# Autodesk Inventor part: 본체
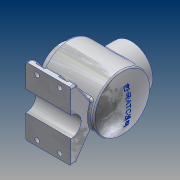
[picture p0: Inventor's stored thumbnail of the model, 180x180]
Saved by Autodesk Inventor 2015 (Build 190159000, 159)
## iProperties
Created: 2017-04
Part Number: 본체
Material: 알루미늄 6061
Document SubType Name: Modeling
Designer: owner
Density: 2.7 g/cm^3
Appearance: 알루미늄 - 평지
Mass: 1664.46 g
Surface Area: 1066.88 cm^2
Volume: 616.468 cm^3
Author: owner
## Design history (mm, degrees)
sketch "스케치1"
  geometry: L1 (-60, 0)-(60, 0); L2 (-60, 0)-(-60, 38); L3 (-60, 38)-(-51, 38); L4 (-48, 41)-(-48, 47); L5 (-45, 50)-(46.454, 50); L6 (-60, 27)-(-38, 27); L7 (-38, 27)-(-38, 37); L8 (-35, 40)-(39.903, 40); L9 (-53, 7.069)-(-53, -16.62); A1 r 3 centre (-45, 47) between (-45, 50) and (-48, 47); A2 r 3 centre (-51, 41) between (-51, 38) and (-48, 41); A3 r 3 centre (-35, 37) between (-35, 40) and (-38, 37); A4 r 113 centre (-53, 0) between (60, 0) and (49.166, 48.282); A5 r 103 centre (-53, 0) between (50, 0) and (42.69, 38.11); A6 r 3 centre (39.903, 37) between (42.69, 38.11) and (39.903, 40); A7 r 3 centre (46.454, 47) between (49.166, 48.282) and (46.454, 50); 5 further points
  constraints: 18 end point, 16 point on circle, 10 tangent, 8 point on line, 7 centre point, 5 perpendicular, 3 equal radius, 2 coincident, 2 horizontal, 2 vertical, 1 midpoint
  dimensions: "d0" = 120 distance of L1.end L1.start; "d3" = 76 diameter of L3 L1; "d4" = 54 diameter of L6 L1; "d5" = 22 distance of L6.start L6.end; "d6" = 12 distance of L2.end point (-48, 38); "d7" = 100 diameter of L5 L1; "d8" = 80 diameter of L8 L1; "d9" = 3 radius of A1; "d14" = 113 distance from line of L9 L1.end; "d15" = 113 radius of A4 (derived); "d16" = 103 radius of A5; "d17" = 3 radius of A6
revolve "회전1" sketch "스케치1" stored, may be unused: angle "d18" = 90 deg
chamfer "모따기1" distance "d19" = 1; stored, may be unused: second distance "d20" = 2, angle "d21" = 45 deg
node "작업 평면1"
sketch "스케치2"
  geometry: C1 r 38 at (0, 0); C2 r 27 at (0, 0); 1 further point
  constraints: 2 centre point, 2 coincident
  dimensions: "d23" = 76 diameter of C1; "d24" = 54 diameter of C2
extrude "돌출1" join sketch "스케치2" stored distance "d25" = 10; taper "d26" = 0 deg
extrude "돌출2" cut sketch "스케치2" stored distance "d27" = 10; taper "d28" = 0 deg
chamfer "모따기2" distance "d29" = 1; stored, may be unused: second distance "d30" = 2, angle "d31" = 45 deg
sketch "스케치3"
  geometry: C1 r 38 at (0, 0) reference; 1 further point
  constraints: 1 vertical alignment
  dimensions: "d32" = 32.5 distance of C1.centre point (0, 32.5)
hole "구멍1" sketch "스케치3" at (0, 32.5) diameter "d33" = 3.242; stored, may be unused: countersink angle "d37" = 90 deg, drill point angle "d39" = 118 deg; dims "d34" = 8, "d35" = 4, "d36" = 2, "d38" = 10
sketch "스케치4"
  geometry: C1 r 38 at (0, 0) reference; 1 further point
  constraints: 1 vertical alignment
  dimensions: "d43" = 32.5 distance of C1.centre point (0, 32.5)
hole "구멍2" sketch "스케치4" at (0, 32.5) diameter "d44" = 3.242; stored, may be unused: countersink angle "d48" = 90 deg, drill point angle "d50" = 118 deg; dims "d45" = 8, "d46" = 4, "d47" = 2, "d49" = 10
sketch "스케치5"
  geometry: L1 (-82, -60)-(-72, -60); L2 (-72, -60)-(-45.101, -21.584); L3 (-82, 60)-(-72, 60); L4 (-72, 60)-(-45.101, 21.584); L5 (-82, -60)-(-82, -18); L6 (-82, 18)-(-82, 60); A1 r 50 centre (0, 0) between (-45.101, -21.584) and (-45.101, 21.584) reference; A2 r 18 centre (-82, 0) between (-82, -18) and (-82, 18); 2 further points
  constraints: 12 end point, 4 point on circle, 2 horizontal, 2 vertical, 1 centre point, 1 coincident, 1 collinear, 1 horizontal alignment
  dimensions: "d54" = 120 distance of L1.start L3.start; "d56" = 10 distance of L1.start L1.end; "d57" = 36 diameter of A2; "d58" = 82 distance from line of L6 point (0, 0); "d59" = 82 distance of point (-82, 0) point (0, 0); "d60" = 10 distance from line of L6 L3.end; "d61" = 55 deg angle of L1 L2; "d62" = 55 deg angle of L3 L4; "d63" = 38.41556 vertical distance of L3.end L4.end
extrude "돌출3" join sketch "스케치5" stored distance "d64" = 80; taper "d65" = 0 deg
sketch "스케치6"
  geometry: L1 (80, 0)-(0, 0) reference; L2 (20, -15.656)-(20, 10); L3 (28, 0)-(28, 10); L4 (12, 10)-(12, 0); L5 (12, 0)-(28, 0); C1 r 4 at (20, 10); A1 r 8 centre (20, -15.656) between (12, -15.656) and (28, -15.656); A2 r 8 centre (20, 10) between (28, 10) and (12, 10); 2 further points
  constraints: 10 end point, 4 point on circle, 4 tangent, 3 centre point, 2 point on line, 1 coincident, 1 collinear, 1 midpoint, 1 parallel, 1 perpendicular
  dimensions: "d67" = 20 horizontal distance of point (40, 60) point (20, -2.828); "d68" = 16 distance between parallel lines of L4 L3; "d70" = 10 distance from line of L1 L2.end; "d71" = 8 diameter of C1
extrude "돌출4" cut sketch "스케치6" distance "d72" = 6; taper "d73" = 0 deg
node "작업 평면2"
sketch "스케치7"
  geometry: L1 (20, -75.675)-(20, -50); L2 (28, -60)-(28, -50); L3 (12, -50)-(12, -60); L4 (-40, -60)-(40, -60) reference; L5 (12, -60)-(28, -60); A1 r 8 centre (20, -75.675) between (12, -75.675) and (28, -75.675); A2 r 8 centre (20, -50) between (28, -50) and (12, -50); 2 further points
  constraints: 10 end point, 4 point on circle, 4 tangent, 2 centre point, 2 point on line, 1 midpoint, 1 parallel, 1 vertical
  dimensions: "d75" = 20 horizontal distance of point (20, -62.837) point (0, 0); "d76" = 16 distance between parallel lines of L2 L3; "d77" = 10 distance from line of L4 L1.end
extrude "돌출5" cut sketch "스케치7" stored distance "d78" = 6; taper "d79" = 0 deg
fillet "모깎기1" dims "d80" = 3
fillet "모깎기2" dims "d81" = 3
node "작업 평면3"
sketch "스케치8"
  geometry: 2 further points
  constraints: 1 coincident, 1 other
feature "엠보싱1" sketch "스케치8" dims "d0" = 120, "d3" = 76, "d4" = 54, "d5" = 22, "d6" = 12, "d7" = 100, "d8" = 80, "d9" = 3, "d14" = 113, "d15" = 113 (derived), "d16" = 103, "d17" = 3, "d83" = 0.5, "d84" = 0
node "솔리드1"
pattern_circular "원형 패턴1" dims angle "d41" = 360 deg
pattern_circular "원형 패턴2" dims angle "d52" = 360 deg
mirror "대칭1"
mirror "대칭2"
other parameters: "d22" = 65, "d55" = 82, "d74" = -76, "d82" = 60.5
